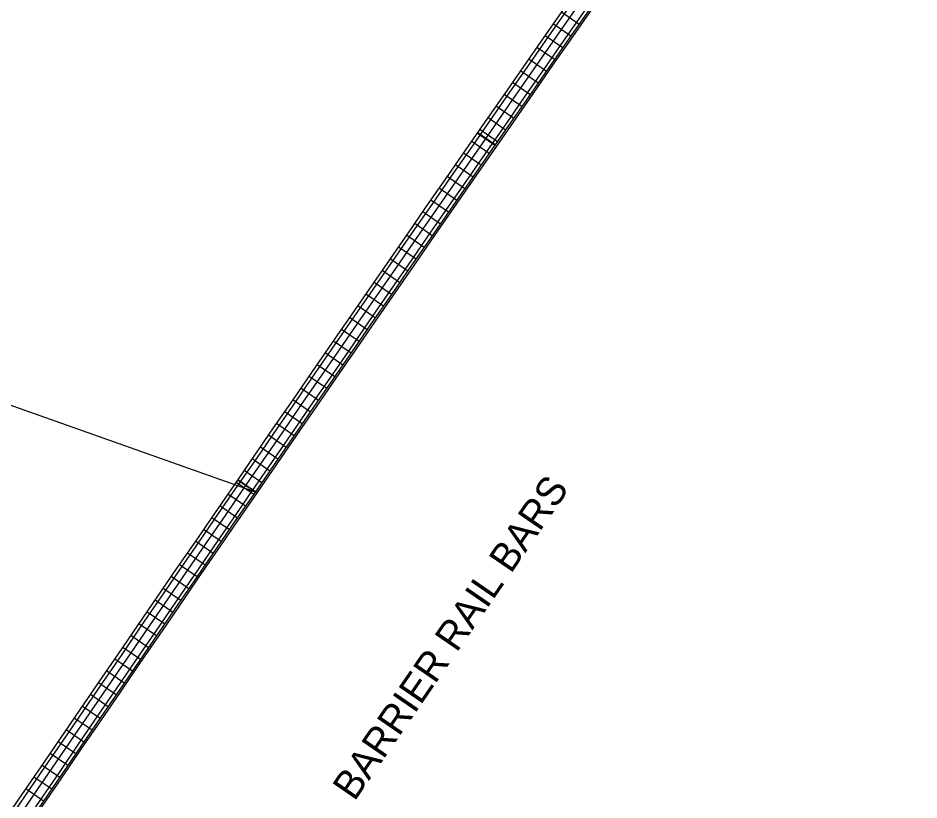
# Model space of a CAD drawing. Extents: x 2378999 to 2381348, y 331302 to 333122.
# Drawn here: x 2379971 to 2380034.1, y 332214.8 to 332269.5 of the extents above; entities that cross this region are included whole.
import ezdxf

# ---------------------------------------------------------------- set-up
doc = ezdxf.new("R2010")
doc.units = 0
for name, color, linetype in [('Dimension Lines', 7, 'Continuous'), ('Mis Work Point CELL', 7, 'Continuous'), ('P_SMU_Centerline_Joint', 7, 'Continuous'), ('P_SMU_Concrete_Barrier_Rail', 7, 'Continuous'), ('P_SMU_Mis_Center_Lines', 7, 'Continuous'), ('Scratch_Level_0', 7, 'Continuous'), ('Sup Concrete Slab Lines', 7, 'Continuous')]:
    doc.layers.add(name, color=color, linetype=linetype)

msp = doc.modelspace()

# ---------------------------------------------------------------- linework, layer by layer
at = {"layer": 'Dimension Lines'}
for p, q in [((2380009.066, 332269.906), (2380010.297, 332269.049)), ((2380008.494, 332269.085), (2380009.725, 332268.228)), ((2380007.923, 332268.264), (2380009.154, 332267.407)), ((2380007.351, 332267.443), (2380008.583, 332266.587)), ((2380006.78, 332266.622), (2380008.012, 332265.766)), ((2380006.209, 332265.801), (2380007.441, 332264.945)), ((2380005.638, 332264.98), (2380006.87, 332264.124)), ((2380005.067, 332264.159), (2380006.299, 332263.303)), ((2380004.496, 332263.337), (2380005.728, 332262.481)), ((2380003.926, 332262.516), (2380005.158, 332261.66)), ((2380003.355, 332261.694), (2380004.587, 332260.839)), ((2380002.785, 332260.873), (2380004.017, 332260.017)), ((2380002.215, 332260.051), (2380003.447, 332259.196)), ((2380001.644, 332259.229), (2380002.877, 332258.374)), ((2380001.074, 332258.407), (2380002.307, 332257.553)), ((2380000.504, 332257.585), (2380001.737, 332256.731)), ((2379999.934, 332256.763), (2380001.167, 332255.909)), ((2379999.365, 332255.941), (2380000.598, 332255.087)), ((2379998.795, 332255.119), (2380000.028, 332254.265)), ((2379998.226, 332254.297), (2379999.459, 332253.443)), ((2379997.656, 332253.475), (2379998.89, 332252.621)), ((2379997.087, 332252.652), (2379998.32, 332251.799)), ((2379996.518, 332251.83), (2379997.751, 332250.976)), ((2379995.949, 332251.007), (2379997.183, 332250.154)), ((2379995.38, 332250.184), (2379996.614, 332249.331)), ((2379994.811, 332249.362), (2379996.045, 332248.509)), ((2379994.243, 332248.539), (2379995.477, 332247.686)), ((2379993.674, 332247.716), (2379994.908, 332246.863)), ((2379993.106, 332246.893), (2379994.34, 332246.041)), ((2379992.537, 332246.07), (2379993.772, 332245.218)), ((2379991.969, 332245.247), (2379993.204, 332244.395)), ((2379991.401, 332244.423), (2379992.636, 332243.572)), ((2379990.833, 332243.6), (2379992.068, 332242.749)), ((2379990.265, 332242.777), (2379991.5, 332241.925)), ((2379989.697, 332241.953), (2379990.932, 332241.102)), ((2379989.13, 332241.13), (2379990.365, 332240.279)), ((2379988.562, 332240.306), (2379989.798, 332239.455)), ((2379987.995, 332239.482), (2379989.23, 332238.632)), ((2379987.428, 332238.659), (2379988.663, 332237.808)), ((2379986.86, 332237.835), (2379988.096, 332236.984)), ((2379986.293, 332237.011), (2379987.529, 332236.161)), ((2379985.727, 332236.187), (2379986.962, 332235.337)), ((2379985.16, 332235.363), (2379986.396, 332234.513)), ((2379984.593, 332234.538), (2379985.829, 332233.689)), ((2379984.026, 332233.714), (2379985.263, 332232.865)), ((2379983.46, 332232.89), (2379984.696, 332232.04)), ((2379982.894, 332232.065), (2379984.13, 332231.216)), ((2379982.327, 332231.241), (2379983.564, 332230.392)), ((2379981.761, 332230.416), (2379982.998, 332229.567)), ((2379981.195, 332229.592), (2379982.432, 332228.743)), ((2379980.629, 332228.767), (2379981.866, 332227.918)), ((2379980.064, 332227.942), (2379981.301, 332227.094)), ((2379979.498, 332227.117), (2379980.735, 332226.269)), ((2379978.933, 332226.292), (2379980.17, 332225.444)), ((2379978.367, 332225.467), (2379979.605, 332224.619)), ((2379977.802, 332224.642), (2379979.039, 332223.794)), ((2379977.237, 332223.817), (2379978.474, 332222.969)), ((2379976.672, 332222.991), (2379977.909, 332222.144)), ((2379976.107, 332222.166), (2379977.345, 332221.319)), ((2379975.542, 332221.341), (2379976.78, 332220.494)), ((2379974.977, 332220.515), (2379976.215, 332219.668)), ((2379974.413, 332219.689), (2379975.651, 332218.843)), ((2379973.848, 332218.864), (2379975.087, 332218.017)), ((2379973.284, 332218.038), (2379974.522, 332217.192)), ((2379972.72, 332217.212), (2379973.958, 332216.366)), ((2379972.155, 332216.386), (2379973.394, 332215.54)), ((2379971.591, 332215.56), (2379972.83, 332214.714))]:
    msp.add_line(p, q, dxfattribs=at)
at = {"layer": 'Mis Work Point CELL'}
msp.add_line((2379949.465, 332249.85), (2379987.771, 332236.292), dxfattribs=at)
at = {"layer": 'P_SMU_Centerline_Joint'}
for p, q in [((2380003.19, 332261.456), (2380004.422, 332260.6)), ((2379986.412, 332237.184), (2379987.648, 332236.333))]:
    msp.add_line(p, q, dxfattribs=at)
at = {"layer": 'P_SMU_Concrete_Barrier_Rail'}
for centre, radius, start, end in [((2385921.515, 328197.486), 7099.625, 143.7189557, 147.2996841), ((2385804.082, 328233.864), 7099.625, 144.9264379, 146.1770793), ((2385804.082, 328233.864), 7060.375, 144.8375893, 146.0956843)]:
    msp.add_arc(centre, radius, start, end, dxfattribs=at)
at = {"layer": 'P_SMU_Mis_Center_Lines'}
for p, q in [((2380003.202, 332261.473), (2380004.434, 332260.618)), ((2380003.178, 332261.439), (2380004.41, 332260.583)), ((2379986.401, 332237.166), (2379987.636, 332236.316)), ((2379986.424, 332237.201), (2379987.66, 332236.35))]:
    msp.add_line(p, q, dxfattribs=at)
for radius, start, end in [(7099.5, 144.9331384, 146.16988), (7098, 144.9297631, 146.1667848), (7098.688, 144.9473125, 146.1519319), (7062, 144.8483099, 146.0920919), (7060.5, 144.8448973, 146.0889626), (7061.313, 144.8631161, 146.0745602)]:
    msp.add_arc((2385804.082, 328233.864), radius, start, end, dxfattribs=at)
at = {"layer": 'Scratch_Level_0'}
for radius, start, end in [(7099.271, 144.9340192, 146.1680189), (7098.229, 144.9316755, 146.1658692), (7061.771, 144.849193, 146.0902177), (7060.729, 144.8468234, 146.0880443)]:
    msp.add_arc((2385804.082, 328233.864), radius, start, end, dxfattribs=at)

# ---------------------------------------------------------------- texts
at = {"layer": 'Sup Concrete Slab Lines'}
msp.add_text('BARRIER RAIL BARS', height=2, rotation=55.50932, dxfattribs=at).set_placement((2379994.579, 332214.621))

doc.saveas('drawing.dxf')
